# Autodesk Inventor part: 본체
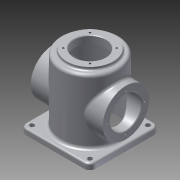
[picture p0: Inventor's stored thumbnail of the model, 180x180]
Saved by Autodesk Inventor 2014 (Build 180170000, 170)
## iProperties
Created: 2015-10
Part Number: 본체
Material: Aluminum 6061
Document SubType Name: Modeling
Designer: user
Density: 2.71 g/cm^3
Appearance: Aluminum - Flat
Mass: 984.45 g
Surface Area: 1036.06 cm^2
Volume: 363.266 cm^3
Author: user
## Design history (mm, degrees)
sketch "Sketch1"
  geometry: C1 r 50 at (0, 0); 1 further point
  constraints: 1 centre point, 1 coincident
extrude "Extrusion1" new body sketch "Sketch1" distance "d0" = 110; taper "d1" = 0 deg
sketch "Sketch2"
  geometry: L1 (-59.762, 60)-(59.762, 60); L2 (59.762, 60)-(59.762, -60); L3 (59.762, -60)-(-59.762, -60); L4 (-59.762, -60)-(-59.762, 60); C1 r 50 at (0, 0) reference; 2 further points
  constraints: 8 end point, 2 midpoint, 1 horizontal alignment, 1 vertical alignment
extrude "Extrusion2" join sketch "Sketch2" distance "d2" = 10; taper "d3" = 0 deg
sketch "Sketch3"
  geometry: L1 (-60, -10)-(60, -10) reference; C1 r 40 at (0, 50); 1 further point
  constraints: 1 centre point
  dimensions: "d4" = 80 diameter of C1; "d5" = 60 distance from line of L1 C1.centre
extrude "Extrusion3" join sketch "Sketch3" stored distance "d6" = 124; taper "d7" = 0 deg
sketch "Sketch4"
  geometry: C1 r 50 at (0, 0) reference; C2 r 40 at (0, 0)
  constraints: 1 centre point, 1 coincident
extrude "Extrusion4" join sketch "Sketch4" distance "d8" = 5; taper "d9" = 0 deg
sketch "Sketch5"
  geometry: C1 r 45 at (0, 0); 1 further point
  constraints: 1 centre point, 1 coincident
extrude "Extrusion5" cut sketch "Sketch5" distance "d10" = 112; taper "d11" = 0 deg
hole "Hole1" diameter "d14" = 54; stored, may be unused: countersink angle "d18" = 90 deg, drill point angle "d20" = 118 deg; dims "d12" = 10, "d13" = 10, "d15" = 6, "d16" = 4, "d17" = 2, "d19" = 8
hole "Hole2" diameter "d23" = 54; stored, may be unused: countersink angle "d27" = 90 deg, drill point angle "d29" = 118 deg; dims "d21" = 10, "d22" = 10, "d24" = 6, "d25" = 4, "d26" = 2, "d28" = 8
fillet "Fillet1" dims "d30" = 10
sketch "Sketch6"
  geometry: A1 r 10 centre (49.762, -50) between (49.762, -60) and (59.762, -50) reference; A2 r 10 centre (49.762, 50) between (59.762, 50) and (49.762, 60) reference; A3 r 10 centre (-49.762, 50) between (-49.762, 60) and (-59.762, 50) reference; A4 r 10 centre (-49.762, -50) between (-59.762, -50) and (-49.762, -60) reference
hole "Hole3" sketch "Sketch6" at (-49.762, -50), (49.762, -50), (-49.762, 50), (49.762, 50) diameter "d31" = 8; stored, may be unused: countersink angle "d35" = 90 deg, drill point angle "d37" = 118 deg; dims "d32" = 6, "d33" = 4, "d34" = 2, "d36" = 8
sketch "Sketch7"
  geometry: C1 r 40 at (0, 0) reference; A1 r 32.5 centre (0, 0) between (0, 32.5) and (-32.5, 0); 3 further points
  constraints: 4 point on circle, 1 centre point, 1 coincident
hole "Hole4" sketch "Sketch7" at (0, 32.5), (-32.5, 0), (32.5, 0), (0, -32.5) diameter "d38" = 3.242; stored, may be unused: countersink angle "d42" = 90 deg, drill point angle "d44" = 118 deg; dims "d39" = 8, "d40" = 4, "d41" = 2, "d43" = 10
mirror "Mirror1"
sketch "Sketch8" dims "d46" = 65
  geometry: L1 (0, 0)-(0, 50); L2 (0, 0)-(-39.286, 39.286); C1 r 40 at (0, 0) reference; 2 further points
  constraints: 4 end point, 1 coincident, 1 point on line, 1 vertical alignment, 4 other
  dimensions: "d45" = 45 deg angle of L1 L2
hole "Hole5" sketch "Sketch8" at (-22.981, 22.981) diameter "d47" = 3.242; stored, may be unused: countersink angle "d51" = 90 deg, drill point angle "d53" = 118 deg; dims "d48" = 8, "d49" = 4, "d50" = 2, "d52" = 10
pattern_circular "Circular Pattern1" dims angle "d55" = 360 deg
workplane "Work Plane1"
sketch "Sketch9"
  geometry: L1 (-49.762, 0)-(49.762, 0) reference; L2 (49.762, -10)-(-49.762, -10) reference; 3 further points
  constraints: 1 midpoint, 1 vertical alignment, 1 other
  dimensions: "d57" = 70 distance from line of L2 point (0, 60)
emboss "Emboss1" sketch "Sketch9" dims "d58" = 0.5, "d59" = 0
fillet "Fillet2" dims "d60" = 5
fillet "Fillet3" dims "d61" = 3
chamfer "Chamfer1" distance "d62" = 3; stored, may be unused: second distance "d63" = 2, angle "d64" = 45 deg
chamfer "Chamfer2" distance "d65" = 1; stored, may be unused: second distance "d66" = 2, angle "d67" = 45 deg
chamfer "Chamfer3" distance "d68" = 1; stored, may be unused: second distance "d69" = 2, angle "d70" = 45 deg
body "Solid1"
